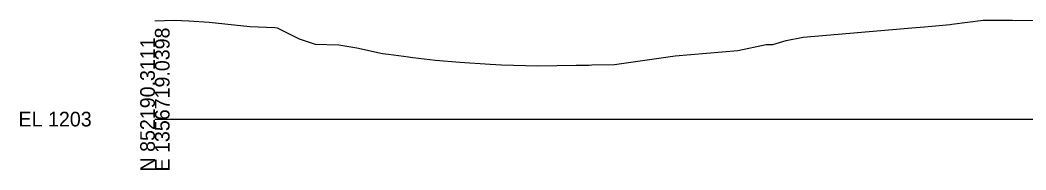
# Model space of a CAD drawing. Extents: x -26 to 4603, y -10 to 4066.
# Drawn here: x -25.7 to 166.1, y 3490.3 to 3518.9 of the extents above; entities that cross this region are included whole.
import ezdxf

# ---------------------------------------------------------------- set-up
doc = ezdxf.new("R2010")
doc.units = 0
doc.layers.add('Exist Cross Section Cell', color=7, linetype='Continuous')
doc.layers.add('Exist XS Ground Line', color=7, linetype='Continuous')

msp = doc.modelspace()

# ---------------------------------------------------------------- linework, layer by layer
at = {"layer": 'Exist Cross Section Cell'}
msp.add_line((0, 3500), (200, 3500), dxfattribs=at)
at = {"layer": 'Exist XS Ground Line'}
for p, q in [((0, 3518.75), (3.7, 3518.9)), ((3.7, 3518.9), (6.49, 3518.77)), ((6.49, 3518.77), (10.34, 3518.53)), ((151.92, 3518.1), (157.92, 3518.9)), ((157.92, 3518.9), (163.5, 3518.87)), ((163.5, 3518.87), (174.59, 3518.84)), ((10.34, 3518.53), (18.12, 3517.65)), ((18.12, 3517.65), (22.89, 3517.48)), ((22.89, 3517.48), (23.31, 3517.4)), ((23.31, 3517.4), (27.5, 3515.33)), ((123.61, 3515.67), (145.08, 3517.48)), ((145.08, 3517.48), (146.74, 3517.62)), ((146.74, 3517.62), (151.61, 3518.08)), ((151.61, 3518.08), (151.92, 3518.1)), ((27.5, 3515.33), (30.53, 3514.3)), ((117.83, 3514.23), (120.37, 3515.03)), ((120.37, 3515.03), (123.61, 3515.67)), ((30.53, 3514.3), (35.1, 3514.21)), ((35.1, 3514.21), (38.52, 3513.58)), ((38.52, 3513.58), (43.37, 3512.55)), ((99.2, 3512.05), (111.14, 3513.13)), ((111.14, 3513.13), (116.54, 3514.25)), ((116.54, 3514.25), (117.83, 3514.23)), ((43.37, 3512.55), (44.52, 3512.37)), ((44.52, 3512.37), (48.35, 3511.9)), ((48.35, 3511.9), (48.76, 3511.84)), ((48.76, 3511.84), (49.2, 3511.79)), ((49.2, 3511.79), (53.53, 3511.26)), ((53.53, 3511.26), (58.14, 3510.87)), ((87.64, 3510.43), (99.2, 3512.05)), ((58.14, 3510.87), (63.91, 3510.46)), ((63.91, 3510.46), (66.09, 3510.37)), ((66.09, 3510.37), (72.92, 3510.14)), ((72.92, 3510.14), (80.31, 3510.27)), ((80.31, 3510.27), (82.2, 3510.33)), ((82.2, 3510.33), (82.81, 3510.32)), ((82.81, 3510.32), (83.33, 3510.34)), ((83.33, 3510.34), (87.64, 3510.43))]:
    msp.add_line(p, q, dxfattribs=at)

# ---------------------------------------------------------------- texts
at = {"layer": 'Exist Cross Section Cell'}
for s, p in [('E 1356719.0398', (2.8, 3490)), ('N 852190.3111', (0, 3490))]:
    msp.add_text(s, height=2.8, rotation=90, dxfattribs=at).set_placement(p)
msp.add_text('EL 1203', height=2.8, dxfattribs=at).set_placement((-26, 3498.6))

doc.saveas('drawing.dxf')
